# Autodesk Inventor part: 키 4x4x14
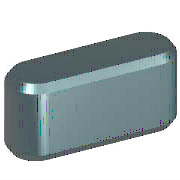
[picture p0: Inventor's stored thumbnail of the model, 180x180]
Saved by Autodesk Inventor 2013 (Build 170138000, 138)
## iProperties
Created: 2012-02
Part Number: 키 4x4x14
Material: 강철, 연강
Description: 키 및 해당 키홈
Document SubType Name: Modeling
Standard: KS B 1311
Designer: mduedu
Standards Organization: KS
Language: ko-KR
Size Designation: 4 x 4 x 14
Categories: <MemberInstance><Categories><Category DisplayName="샤프트 부품" InternalName="7f7aeb1f-a693-4053-b835-cee3144e0d98" Mnemonic="SHFT"><Category DisplayName="키" Interna
Density: 1 g/cm^3
IsCustomPart: 1
Author: mduedu
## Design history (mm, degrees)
workplane "Work Plane1"
workplane "Work Plane2"
sketch "스케치1"
  geometry: L1 (2, 2)-(12, 2); L2 (12, -2)-(2, -2); L3 (0, 9.4)-(0, -7.4) reference; L4 (-5, 0)-(30, 0) reference; L5 (14, 0)-(14, 7); A1 r 2 centre (2, 0) between (2, 2) and (2, -2); A2 r 2 centre (12, 0) between (12, -2) and (12, 2)
  constraints: 6 end point, 5 point on circle, 4 tangent, 3 point on line, 2 centre point, 1 horizontal, 1 parallel, 1 perpendicular
  dimensions: "d0" = 2 radius of A1 (= 0.5 x PB); "d13" = 2 radius of A2 (= 0.5 x PB); "d14" = 14 distance between parallel lines of L5 L3 (= NLG)
extrude "본체1" new body sketch "스케치1" taper "d3" = 0 deg; stored distance "d4" = 10
workplane "Work Plane3"
body "Solid1"
chamfer "모따기1" distance "d8" = 0.25 (= PHH); stored, may be unused: second distance "d9" = 0.25 (= PHH), angle "d15" = 45 deg
other parameters: "d1" = -2.5 (= -PNT), "d2" = 1.5 (= PH - PNT), "NLG" = 14 [user parameter; used in 3 equation terms], "PB" = 4 [user parameter; used in 2 equation terms], "PNT" = 2.5 [user parameter; used in 2 equation terms], "PH" = 4 [user parameter; used in 1 equation term], "PHH" = 0.25 [user parameter; used in 2 equation terms], "d10" = 0, "d16" = 0, "d17" = 0, "d18" = 0, "PLB2" = 14 (= NLG) [user parameter], "WDMAX" = 12 [user parameter], "PLB1" = 14 (= NLG) [user parameter], "RR" = 0.08 [user parameter], "PUEB" = 1.8 [user parameter]
